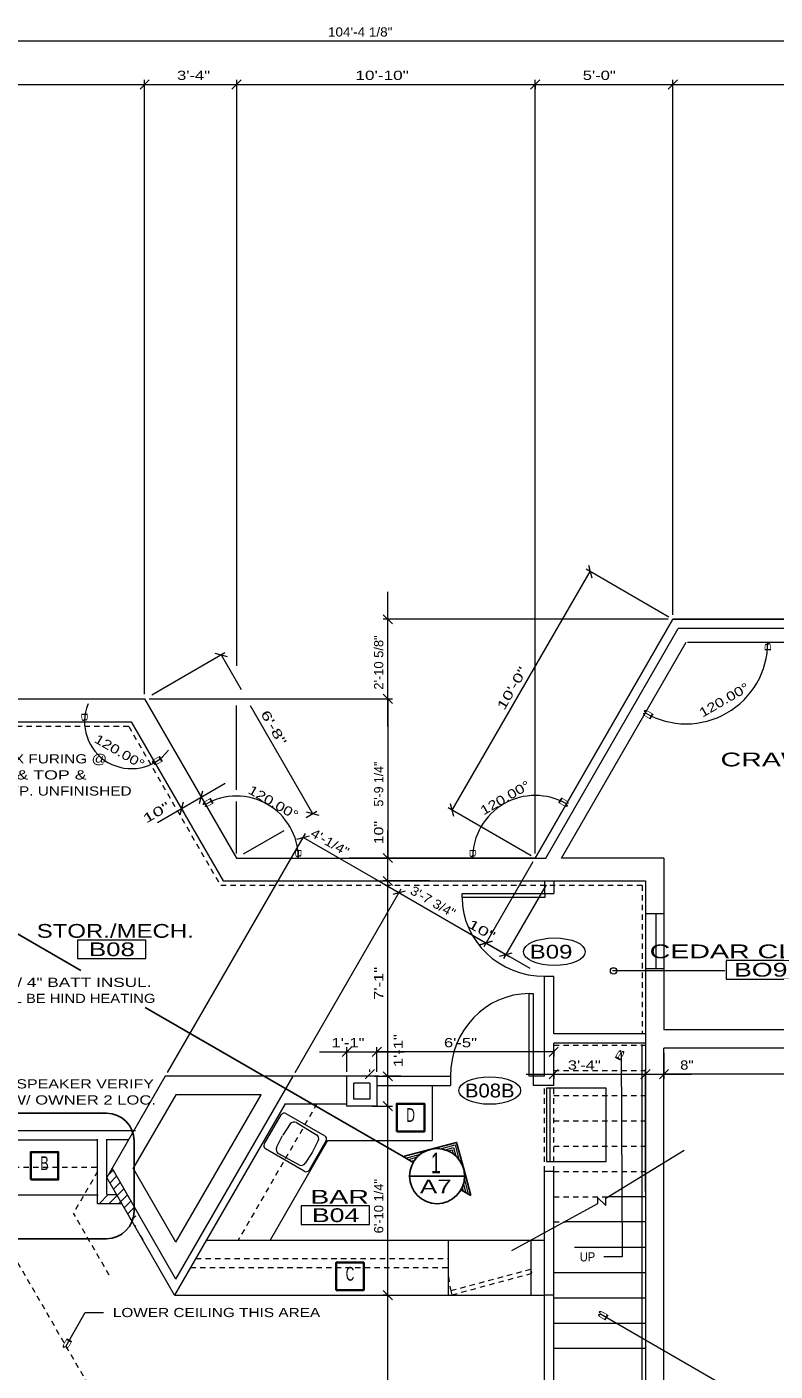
# Model space of a CAD drawing. Extents: x 7 to 126, y 6 to 93.
# Drawn here: x 56.6 to 83.75, y 44.6 to 93.37 of the extents above; entities that cross this region are included whole.
import ezdxf
from ezdxf.enums import TextEntityAlignment as Align

# ---------------------------------------------------------------- set-up
doc = ezdxf.new("R2010")
doc.units = 0
doc.header["$LTSCALE"] = 0.13
doc.linetypes.add('SHORT_DASHED', pattern=[2.7, 1.5, -1.2])
for name, color, linetype, lineweight in [('13', 7, 'Continuous', 13), ('14', 7, 'Continuous', 13), ('15', 7, 'Continuous', 13), ('17', 7, 'Continuous', 13), ('20', 7, 'Continuous', 13), ('22', 7, 'SHORT_DASHED', 13), ('24', 7, 'Continuous', 13), ('30', 7, 'Continuous', 13), ('35', 7, 'Continuous', 13), ('36', 7, 'Continuous', 13), ('40', 7, 'Continuous', 13), ('41', 7, 'Continuous', 13), ('42', 7, 'Continuous', 13), ('45', 7, 'Continuous', 13), ('50', 7, 'Continuous', 13), ('53', 7, 'Continuous', 13), ('56', 7, 'Continuous', 13), ('7', 7, 'Continuous', 13)]:
    doc.layers.add(name, color=color, linetype=linetype, lineweight=lineweight)

msp = doc.modelspace()

# ---------------------------------------------------------------- linework, layer by layer
at = {"layer": '13'}
msp.add_line((75.4239, 63.2187), (80.2315, 71.5456), dxfattribs=at)
msp.add_lwpolyline([(113.2426, 75.154), (98.9815, 75.154), (96.8981, 71.5456), (80.2315, 71.5456)], dxfattribs=at)
at = {"layer": '14'}
for p, q in [((61.6176, 55.2982), (59.4984, 51.6276)), ((68.1292, 55.2982), (61.6176, 55.2982)), ((69.3792, 55.2982), (68.1292, 55.2982)), ((69.2959, 55.2982), (69.2959, 54.2149)), ((68.4625, 54.4649), (68.4625, 55.0482)), ((69.0459, 55.0482), (68.4625, 55.0482)), ((69.0459, 55.0482), (69.0459, 54.4649)), ((65.9685, 54.2982), (68.2125, 54.2982)), ((69.0459, 54.4649), (68.4625, 54.4649)), ((60.7125, 49.5247), (60.8069, 49.3613))]:
    msp.add_line(p, q, dxfattribs=at)
for points in [[(115.8724, 34.3511), (77.539, 34.3511), (75.8724, 37.2379), (59.2057, 37.2379), (57.539, 34.3511), (40.8724, 34.3511), (16.7057, 76.209), (22.539, 86.3127), (34.2057, 86.3127), (44.2057, 68.9922), (60.8724, 68.9922)], [(113.4884, 75.4873), (98.789, 75.4873), (96.7057, 71.8789), (80.039, 71.8789), (75.039, 63.2187), (68.2977, 63.2187)], [(60.8724, 68.9922), (64.2057, 63.2187), (75.039, 63.2187)], [(69.2959, 54.2149), (68.2125, 54.2149), (68.2125, 55.2982)], [(65.9685, 54.2982), (61.9625, 47.3596), (59.4984, 51.6276)]]:
    msp.add_lwpolyline(points, dxfattribs=at)
at = {"layer": '15'}
for p, q in [((76.0013, 63.2187), (80.5226, 71.0498)), ((80.5729, 71.0456), (96.6563, 71.0456)), ((75.039, 63.2187), (75.4239, 63.2187)), ((79.7139, 63.2187), (76.0013, 63.2187)), ((79.7139, 63.2187), (79.7139, 56.9873)), ((63.7246, 62.3853), (79.0473, 62.3853)), ((79.0473, 62.3853), (79.0473, 38.0712)), ((79.0417, 61.2083), (79.6979, 61.2083)), ((79.4167, 61.2083), (79.4167, 59.2292)), ((79.0417, 59.2083), (79.6979, 59.2083)), ((93.7139, 56.9873), (79.7139, 56.9873)), ((94.3806, 56.3207), (79.7139, 56.3207)), ((79.7139, 37.4046), (79.7139, 56.3207)), ((62.0106, 47.943), (66.2572, 55.2982)), ((62.0106, 49.2763), (65.1025, 54.6315)), ((62.0106, 47.943), (59.6908, 51.961)), ((62.0106, 49.2763), (60.4606, 51.961))]:
    msp.add_line(p, q, dxfattribs=at)
for points in [[(23.2126, 85.4793), (33.7246, 85.4793), (43.7246, 68.1588), (60.3912, 68.1588), (63.7246, 62.3853)], [(65.1025, 54.6315), (62.0025, 54.6315), (60.4606, 51.961)]]:
    msp.add_lwpolyline(points, dxfattribs=at)
at = {"layer": '17'}
for points in [[(75.3958, 61.9271), (75.3958, 61.7812), (72.3958, 61.7812), (72.3958, 61.9271)], [(74.9679, 55.2982), (74.8221, 55.2982), (74.8221, 58.2982), (74.9679, 58.2982)]]:
    msp.add_lwpolyline(points, close=True, dxfattribs=at)
for centre, major_axis, start_param, end_param in [((75.3958, 61.7812), (-3, 0), 6.2831853, 7.8539816), ((74.8221, 55.2982), (0, 3), 0, 1.5707963)]:
    msp.add_ellipse(centre, major_axis=major_axis, ratio=0.951389, start_param=start_param, end_param=end_param, dxfattribs=at)
at = {"layer": '20', "linetype": 'SHORT_DASHED'}
for p, q in [((75.7139, 56.4313), (79.0473, 56.4313)), ((75.7139, 55.5146), (79.0473, 55.5146)), ((75.7139, 54.5979), (79.0473, 54.5979)), ((75.7139, 53.6813), (79.0473, 53.6813)), ((75.7139, 52.7646), (79.0473, 52.7646)), ((75.7139, 51.8479), (79.0473, 51.8479)), ((75.7139, 50.9313), (77.6979, 50.9313)), ((75.7139, 50.0146), (76.1562, 50.0146))]:
    msp.add_line(p, q, dxfattribs=at)
at = {"layer": '20'}
for p, q in [((79.0473, 50.9313), (77.6979, 50.9313)), ((79.0473, 50.0146), (76.1562, 50.0146)), ((76.464, 49.0979), (79.0473, 49.0979)), ((75.7139, 48.1813), (79.0473, 48.1813)), ((75.7139, 47.2646), (79.0473, 47.2646)), ((75.7139, 46.3479), (79.0473, 46.3479)), ((75.7139, 45.4313), (79.0473, 45.4313))]:
    msp.add_line(p, q, dxfattribs=at)
at = {"layer": '22'}
msp.add_line((55.0345, 50.6771), (61.6389, 39.2379), dxfattribs=at)
at = {"layer": '24', "linetype": 'SHORT_DASHED'}
for p, q in [((60.295, 67.9922), (43.4737, 67.9922)), ((60.295, 67.9922), (63.6283, 62.2187)), ((78.9223, 62.2187), (63.6283, 62.2187)), ((78.9223, 62.2187), (78.9223, 56.8542))]:
    msp.add_line(p, q, dxfattribs=at)
at = {"layer": '24'}
for p, q in [((78.9223, 38.2379), (78.9223, 56.4583)), ((75.7139, 42.5146), (75.7139, 47.375))]:
    msp.add_line(p, q, dxfattribs=at)
msp.add_lwpolyline([(75.7139, 42.5146), (75.3806, 42.5146), (75.3806, 47.375)], dxfattribs=at)
at = {"layer": '30'}
for p, q in [((65.2133, 52.8368), (65.83, 53.905)), ((66.0007, 53.9507), (67.408, 53.1382)), ((66.1557, 53.5703), (65.8872, 53.1684)), ((66.3793, 53.619), (67.1125, 53.1772)), ((65.663, 52.7169), (65.8768, 53.1504)), ((67.4538, 52.9675), (66.8371, 51.8993)), ((66.9577, 52.5504), (67.1741, 52.9571)), ((66.6663, 51.8535), (65.259, 52.666)), ((65.7326, 52.499), (66.4818, 52.0849)), ((66.9473, 52.5324), (66.7033, 52.1416))]:
    msp.add_line(p, q, dxfattribs=at)
for centre, radius, start, end in [((65.9383, 53.8425), 0.125, 60, 150), ((66.2933, 53.4762), 0.1667, 58.93024, 145.61656), ((67.0265, 53.0344), 0.1667, 332.33731, 58.93024), ((65.3215, 52.7743), 0.125, 150, 240), ((65.8133, 52.6449), 0.1667, 154.38344, 241.06976), ((67.3455, 53.03), 0.125, 330, 60), ((66.5625, 52.2308), 0.1667, 241.06976, 327.66269), ((66.7288, 51.9618), 0.125, 240, 330)]:
    msp.add_arc(centre, radius, start, end, dxfattribs=at)
at = {"layer": '35'}
for p, q in [((71.3013, 54.9649), (71.3013, 52.9649)), ((67.5081, 52.9649), (65.4266, 49.3596)), ((67.5081, 52.9649), (71.3013, 52.9649)), ((55.4271, 51), (59.1651, 51)), ((63.1172, 49.3596), (75.3806, 49.3596)), ((71.8806, 49.3596), (71.8806, 47.3768)), ((74.8806, 49.3596), (74.8806, 47.3768)), ((61.9625, 47.3596), (75.3806, 47.3596))]:
    msp.add_line(p, q, dxfattribs=at)
at = {"layer": '35', "linetype": 'SHORT_DASHED'}
for p, q in [((67.1232, 54.2982), (64.2719, 49.3596)), ((55.4271, 52), (59.1651, 52)), ((62.5399, 48.3596), (71.8806, 48.3596)), ((62.7323, 48.693), (71.8806, 48.693))]:
    msp.add_line(p, q, dxfattribs=at)
msp.add_lwpolyline([(74.9218, 48.1509), (74.8841, 48.2918), (71.9863, 47.5153), (72.024, 47.3744)], close=True, dxfattribs=at)
msp.add_ellipse((74.8841, 48.2918), major_axis=(-2.8978, -0.7765), ratio=0.951389, start_param=6.0980881, end_param=6.2831853, dxfattribs=at)
at = {"layer": '36'}
msp.add_line((75.5755, 54.8561), (75.5755, 52.2023), dxfattribs=at)
msp.add_line((75.5755, 54.8561), (75.5755, 52.2023), dxfattribs=at)
msp.add_lwpolyline([(75.4549, 52.2023), (77.6216, 52.2023), (77.6216, 54.8689), (75.4549, 54.8689)], close=True, dxfattribs=at)
msp.add_lwpolyline([(75.4549, 52.2023), (77.6216, 52.2023), (77.6216, 54.8689), (75.4549, 54.8689)], close=True, dxfattribs=at)
at = {"layer": '40', "lineweight": 25}
for p, q in [((44.0104, 67.5385), (58.5628, 59.1367)), ((70.2579, 52.3845), (60.8886, 57.7939)), ((50.3229, 53.9583), (59.4896, 53.9583)), ((60.4896, 52.9583), (60.4896, 50.4062)), ((70.2579, 52.3845), (71.2238, 52.6433)), ((70.2579, 52.3845), (70.6166, 52.1774)), ((72.4486, 51.9362), (72.7074, 50.9703)), ((70.4827, 51.6774), (72.4827, 51.6774)), ((72.3487, 51.1774), (72.7074, 50.9703)), ((59.4896, 49.4062), (50.3229, 49.4062))]:
    msp.add_line(p, q, dxfattribs=at)
at = {"layer": '40'}
for p, q in [((81.9167, 59.125), (77.8438, 59.125)), ((70.3498, 52.3315), (70.8762, 52.4726)), ((70.4416, 52.2785), (70.7538, 52.3621)), ((70.5335, 52.2254), (70.6716, 52.2624)), ((72.3948, 51.2676), (72.4318, 51.1294)), ((72.44, 51.3886), (72.5237, 51.0764)), ((72.4745, 51.5498), (72.6156, 51.0233))]:
    msp.add_line(p, q, dxfattribs=at)
at = {"layer": '40', "linetype": 'SHORT_DASHED'}
for p in [(59.1651, 51.8473), (59.5905, 48.0813)]:
    msp.add_line(p, (58.2906, 50.3328), dxfattribs=at)
at = {"layer": '40', "lineweight": 35}
for points in [[(70.0208, 53.3021), (71.0208, 53.3021), (71.0208, 54.3021), (70.0208, 54.3021)], [(56.7396, 51.5521), (57.7396, 51.5521), (57.7396, 52.5521), (56.7396, 52.5521)], [(67.8229, 47.5417), (68.8229, 47.5417), (68.8229, 48.5417), (67.8229, 48.5417)]]:
    msp.add_lwpolyline(points, close=True, dxfattribs=at)
at = {"layer": '40', "lineweight": 25}
msp.add_lwpolyline([(71.2238, 52.6433), (72.1898, 52.9022), (72.4486, 51.9362)], dxfattribs=at)
at = {"layer": '40'}
for points in [[(71.6103, 52.6692), (72.1367, 52.8103), (72.2778, 52.2838)], [(71.7715, 52.6348), (72.0837, 52.7184), (72.1674, 52.4062)], [(71.8925, 52.5896), (72.0307, 52.6266), (72.0677, 52.4884)]]:
    msp.add_lwpolyline(points, dxfattribs=at)
msp.add_circle((77.8854, 59.125), 0.1146, dxfattribs=at)
at = {"layer": '40', "lineweight": 25}
msp.add_circle((71.4827, 51.6774), 1, dxfattribs=at)
for centre, start, end in [((59.4896, 52.9583), 0, 90), ((59.4896, 50.4062), 270, 0)]:
    msp.add_arc(centre, 1, start, end, dxfattribs=at)
at = {"layer": '41'}
msp.add_lwpolyline([(74.1968, 48.9808), (77.3168, 50.6859), (77.3168, 50.8957), (77.6034, 50.6091), (77.6034, 50.8792), (80.4428, 52.6148)], dxfattribs=at)
at = {"layer": '42'}
for centre in [(75.7394, 59.8195), (73.394, 54.7829)]:
    msp.add_ellipse(centre, major_axis=(1.1204, 0), ratio=0.446291, dxfattribs=at)
at = {"layer": '45'}
for points in [[(58.4373, 59.5704), (60.9224, 59.5704), (60.9224, 60.2411), (58.4373, 60.2411)], [(81.9754, 58.8277), (84.4605, 58.8277), (84.4605, 59.4984), (81.9754, 59.4984)], [(66.5521, 49.9231), (69.0373, 49.9231), (69.0373, 50.5938), (66.5521, 50.5938)]]:
    msp.add_lwpolyline(points, close=True, dxfattribs=at)
at = {"layer": '50'}
for p, q in [((121.0473, 92.8542), (16.7057, 92.8542)), ((44.2057, 91.2812), (60.8724, 91.2812)), ((59.8724, 91.2812), (65.2057, 91.2812)), ((61.039, 91.4479), (60.7057, 91.1146)), ((61.039, 91.4479), (60.7057, 91.1146)), ((60.8724, 69.1588), (60.8724, 91.4479)), ((64.039, 91.1146), (64.3724, 91.4479)), ((64.039, 91.1146), (64.3724, 91.4479)), ((64.2057, 91.4479), (64.2057, 70.1875)), ((64.2057, 91.2812), (75.039, 91.2812)), ((74.8724, 91.1146), (75.2057, 91.4479)), ((75.2057, 91.4479), (74.8724, 91.1146)), ((75.039, 63.3853), (75.039, 91.4479)), ((75.039, 91.2812), (80.039, 91.2812)), ((75.039, 91.2812), (75.039, 91.1146)), ((80.2057, 91.4479), (79.8724, 91.1146)), ((79.8724, 91.1146), (80.2057, 91.4479)), ((80.039, 72.0456), (80.039, 91.4479)), ((80.039, 91.2812), (96.7057, 91.2812)), ((79.8947, 71.9622), (76.889, 73.6976)), ((76.9723, 73.8419), (77.0944, 73.3866)), ((72.0333, 64.954), (77.0333, 73.6142)), ((69.6979, 67.9922), (69.6979, 72.8789)), ((69.8646, 71.7122), (69.5312, 72.0456)), ((79.8724, 71.8789), (69.5312, 71.8789)), ((61.1305, 69.1412), (63.7885, 70.6758)), ((63.4165, 70.6535), (63.8719, 70.5315)), ((63.6442, 70.5925), (64.3735, 69.3293)), ((61.039, 68.9922), (69.8646, 68.9922)), ((69.5312, 69.1588), (69.8646, 68.8255)), ((69.5312, 69.1588), (69.8646, 68.8255)), ((69.6979, 68.9922), (69.6979, 63.2187)), ((64.2057, 65.6875), (64.2057, 68.75)), ((66.9775, 64.819), (64.7107, 68.7453)), ((61.3421, 64.5119), (63.7958, 65.9286)), ((62.6224, 65.9611), (63.0131, 65.2843)), ((62.8688, 65.2009), (62.9908, 65.6563)), ((62.1412, 65.1277), (62.2914, 64.8676)), ((62.2691, 65.2396), (62.1471, 64.7843)), ((64.2057, 63.3853), (64.2057, 65.2708)), ((67.1219, 64.9023), (66.7307, 64.6765)), ((67.2052, 64.758), (66.7499, 64.88)), ((74.8947, 63.302), (71.889, 65.0373)), ((72.0944, 64.7263), (71.9723, 65.1817)), ((61.7009, 55.4425), (66.7059, 64.1114)), ((64.4639, 63.3677), (65.9331, 64.216)), ((66.3949, 63.906), (66.8502, 64.028)), ((70.1022, 61.958), (66.6226, 63.967)), ((69.6979, 61.3853), (69.6979, 64.2187)), ((69.8646, 63.052), (69.5312, 63.3853)), ((69.8646, 63.052), (69.5312, 63.3853)), ((69.789, 63.2187), (69.8646, 63.2187)), ((74.9557, 63.0743), (73.1756, 59.9912)), ((69.2362, 62.458), (74.125, 59.6355)), ((69.5312, 62.552), (69.8646, 62.2187)), ((69.5312, 62.552), (69.8646, 62.2187)), ((69.5312, 62.552), (69.8646, 62.2187)), ((66.3405, 55.4425), (70.1856, 62.1024)), ((71.2192, 62.3853), (69.5312, 62.3853)), ((69.6979, 55.2982), (69.6979, 62.3853)), ((69.789, 62.3853), (69.8646, 62.3853)), ((70.3299, 62.019), (69.8746, 61.897)), ((70.3299, 62.019), (69.8746, 61.897)), ((75.4368, 62.241), (73.8973, 59.5745)), ((72.3929, 60.6355), (74.8467, 59.2188)), ((73.4866, 60.1965), (73.0313, 60.0745)), ((73.0313, 60.0745), (73.4866, 60.1965)), ((73.753, 59.6578), (74.2083, 59.7798)), ((73.753, 59.6578), (74.2083, 59.7798)), ((67.2125, 56.1875), (70.2959, 56.1875)), ((68.3792, 56.3542), (68.0459, 56.0208)), ((68.2125, 55.4649), (68.2125, 56.3542)), ((69.1292, 56.0208), (69.4625, 56.3542)), ((69.1292, 56.0208), (69.4625, 56.3542)), ((69.2959, 55.4649), (69.2959, 56.3542)), ((75.7139, 56.1875), (69.2959, 56.1875)), ((69.6979, 53.2149), (69.6979, 56.2982)), ((75.8806, 56.3542), (75.5473, 56.0208)), ((75.7139, 56.2646), (75.7139, 56.0208)), ((79.7139, 56.154), (79.7139, 55.2083)), ((68.8792, 55.2083), (69.2125, 55.5417)), ((69.0459, 55.4649), (69.0459, 55.5417)), ((69.2125, 55.2982), (69.8646, 55.2982)), ((69.8646, 55.1315), (69.5312, 55.4649)), ((69.8646, 55.1315), (69.5312, 55.4649)), ((69.8646, 55.1315), (69.5312, 55.4649)), ((70.174, 55.2982), (69.5312, 55.2982)), ((69.6979, 53.0482), (69.6979, 55.2982)), ((74.7139, 55.375), (80.0473, 55.375)), ((75.8806, 55.5417), (75.5473, 55.2083)), ((75.8806, 55.5417), (75.5473, 55.2083)), ((75.7139, 55.3479), (75.7139, 55.2083)), ((78.0473, 55.375), (80.7139, 55.375)), ((79.2139, 55.5417), (78.8806, 55.2083)), ((78.8806, 55.2083), (79.2139, 55.5417)), ((79.0473, 51.1166), (79.0473, 55.5417)), ((79.5473, 55.2083), (79.8806, 55.5417)), ((79.5473, 55.2083), (79.8806, 55.5417)), ((93.7139, 55.375), (79.7139, 55.375)), ((69.1292, 54.2149), (69.8646, 54.2149)), ((69.5312, 54.3815), (69.8646, 54.0482)), ((69.5312, 54.3815), (69.8646, 54.0482)), ((69.6979, 47.3596), (69.6979, 54.2149)), ((62.1292, 47.3596), (69.8646, 47.3596)), ((69.5312, 47.5263), (69.8646, 47.193)), ((69.8646, 47.193), (69.5312, 47.5263)), ((69.5312, 47.5263), (69.8646, 47.193)), ((69.6979, 47.3596), (69.5312, 47.3596)), ((69.6979, 38.0712), (69.6979, 47.3596))]:
    msp.add_line(p, q, dxfattribs=at)
for points in [[(78.1667, 56.1667), (78.1936, 48.7494), (77.5269, 48.7494)], [(58.0104, 45.5), (58.7202, 46.7294), (59.3869, 46.7294)], [(77.4062, 46.6771), (82.7784, 43.5755), (83.4451, 43.5755)]]:
    msp.add_lwpolyline(points, dxfattribs=at)
for centre, radius, start, end in [((80.5202, 71.0456), 2.9601, 239.99997, 0), ((60.3912, 68.1588), 1.6973, 157.49552, 322.50458), ((64.2057, 63.2187), 2.2466, 0, 119.99992), ((75.039, 63.2187), 2.2684, 59.99997, 180)]:
    msp.add_arc(centre, radius, start, end, dxfattribs=at)
at = {"layer": '53'}
for p, q in [((75.3806, 62.375), (75.3806, 61.9271)), ((75.7139, 62.375), (75.7139, 61.9271)), ((75.3806, 61.9271), (75.7139, 61.9271)), ((75.3806, 58.9271), (75.7188, 58.9271)), ((75.3806, 55.2982), (75.3806, 58.9271)), ((75.7139, 56.8369), (75.7139, 58.9271)), ((79.0473, 56.8369), (75.7139, 56.8369)), ((79.0473, 56.5036), (75.7139, 56.5036)), ((75.7139, 54.9649), (75.7139, 56.5036)), ((69.3792, 55.2982), (71.9688, 55.2982)), ((71.9679, 55.2982), (71.9679, 54.9649)), ((74.9679, 55.2982), (74.9679, 54.9649)), ((75.3806, 55.2982), (74.9679, 55.2982)), ((69.2959, 54.9649), (71.9679, 54.9649)), ((75.7139, 54.9649), (74.9679, 54.9649)), ((54.9271, 53.3333), (60.5417, 53.3333)), ((60.2907, 53), (59.4896, 53)), ((59.4984, 51.0104), (59.4984, 53.0176)), ((75.3806, 47.375), (75.3806, 51.8479)), ((75.7139, 51.8479), (75.3806, 51.8479)), ((75.7139, 47.375), (75.7139, 51.8479)), ((59.4984, 51.0104), (59.8547, 51.0104)), ((75.3806, 47.375), (75.7043, 47.375))]:
    msp.add_line(p, q, dxfattribs=at)
at = {"layer": '53', "linetype": 'SHORT_DASHED'}
for p, q in [((75.3806, 51.8479), (75.3806, 54.9649)), ((75.7139, 51.8479), (75.7139, 54.9649))]:
    msp.add_line(p, q, dxfattribs=at)
at = {"layer": '53'}
for points in [[(55.4271, 50.6771), (55.4271, 53), (59.1651, 53)], [(60.0417, 50.6771), (59.1651, 50.6771), (59.1651, 53.0176)]]:
    msp.add_lwpolyline(points, dxfattribs=at)
at = {"layer": '56'}
for p, q in [((59.5474, 51.7126), (59.7293, 51.8944)), ((59.5726, 50.6771), (60.1175, 51.222)), ((59.6147, 51.4262), (59.8587, 51.6703)), ((59.7441, 51.2021), (59.9881, 51.4461)), ((59.1651, 50.9766), (59.1888, 51.0004)), ((59.2191, 50.6771), (59.5478, 51.0058)), ((59.9262, 50.6771), (60.2469, 50.9978)), ((60.1294, 50.5268), (60.3763, 50.7737)), ((60.2597, 50.3035), (60.5057, 50.5495)), ((60.39, 50.0803), (60.5505, 50.2407)), ((60.5203, 49.857), (60.5505, 49.8872))]:
    msp.add_line(p, q, dxfattribs=at)
at = {"layer": '7'}
msp.add_lwpolyline([(115.8724, 34.3511), (77.539, 34.3511), (75.8724, 37.2379), (59.2057, 37.2379), (57.539, 34.3511), (40.8724, 34.3511), (16.7057, 76.209), (22.539, 86.3127), (34.2057, 86.3127), (44.2057, 68.9922), (60.8724, 68.9922), (64.2057, 63.2187), (65.039, 63.2187), (75.039, 63.2187), (80.039, 71.8789), (96.7057, 71.8789), (98.789, 75.4873), (113.4884, 75.4873), (121.0473, 51.0685)], dxfattribs=at)

# ---------------------------------------------------------------- texts
at = {"layer": '40'}
for s, width, p in [('D', 0.65, (70.3665, 53.6441)), ('B', 0.7, (57.0852, 51.8941)), ('C', 0.65, (68.1686, 47.8837))]:
    msp.add_text(s, height=0.5, dxfattribs=dict(at, width=width)).set_placement(p)
for s, height, width, p in [('1', 0.75, 0.65, (71.4389, 51.7785)), ('A7 ', 0.5, 1.4, (71.5649, 51.0524))]:
    msp.add_text(s, height=height, dxfattribs=dict(at, width=width)).set_placement(p, align=Align.CENTER)
at = {"layer": '42'}
for s, width, p in [('B09 ', 1.3, (75.7394, 59.5695)), ('B08B', 1.1, (73.394, 54.5329))]:
    msp.add_text(s, height=0.5, dxfattribs=dict(at, width=width)).set_placement(p, align=Align.CENTER)
at = {"layer": '45'}
for s, width, p in [('     CRAWL SPACE    ', 1.55, (85.3956, 66.5432)), ('     STOR./MECH.    ', 1.3, (59.6873, 60.3244)), (' B08 ', 1.4, (59.6873, 59.6578)), ('    CEDAR CLOSET    ', 1.55, (83.2254, 59.5817)), (' BO9 ', 1.45, (83.2253, 58.915)), ('         BAR        ', 1.55, (67.8021, 50.6771)), (' B04 ', 1.45, (67.8021, 50.0104))]:
    msp.add_text(s, height=0.5, dxfattribs=dict(at, width=width)).set_placement(p, align=Align.CENTER)
at = {"layer": '50'}
for s, width, p in [('104\'-4 1/8"', 1.1, (67.5248, 93.0208)), ('3\'-4"', 1.35, (62.0494, 91.4479)), ('10\'-10"', 1.4, (68.52, 91.4479)), ('5\'-0"', 1.35, (76.7674, 91.4479)), ('TREATED 2X FURING @ ', 1.25, (53.0658, 66.6506)), ('2\' -0" O.C. & TOP & ', 1.45, (53.0658, 66.0673)), ('BOTTOM TYP. UNFINISHED', 1.25, (53.0658, 65.484)), ('1/2\' G.B. B.S. 2X4 W/ 4" BATT INSUL. ', 1.4, (50.4479, 58.5417)), ('FOR SOUND CONTROL BE HIND HEATING ', 1.2, (50.4479, 57.9583)), ('1\'-1"', 1.35, (67.654, 56.3542)), ('6\'-5"', 1.35, (71.7332, 56.3542)), ('3\'-4"', 1.35, (76.2246, 55.5417)), ('8"', 1.2, (80.3021, 55.5417)), ('BUILT-IN STERO SPEAKER VERIFY ', 1.3, (51.4883, 54.8586)), ('SIZE AND LOC. W/ OWNER 2 LOC. ', 1.35, (51.4883, 54.2753)), ('UP', 0.9, (76.6617, 48.5827)), ('LOWER CEILING THIS AREA', 1.25, (59.7202, 46.5627))]:
    msp.add_text(s, height=0.3333, dxfattribs=dict(at, width=width)).set_placement(p)
for s, rotation, width, p in [('2\'-10 5/8"', 90, 1.05, (69.5312, 69.3255)), ('10\'-0"', 60, 1.5, (73.9205, 68.556)), ('120.00°', 30, 1.3, (81.1115, 68.3077)), ('6\'-8"', 300, 1.55, (65.0694, 68.4573)), ('120.00°', 330, 1.3, (59.0145, 67.4377)), ('120.00°', 30, 1.3, (73.1693, 64.7609)), ('120.00°', 330, 1.3, (64.5952, 65.5887)), ('10"', 30, 1.6, (60.9313, 64.4672)), ('10"', 90, 1.3, (69.5312, 63.7141)), ('4\'-1/4"', 330, 1.2, (66.8621, 64.0212)), ('3\'-7 3/4"', 330, 1.1, (70.4742, 61.9357)), ('10"', 330, 1.6, (72.5644, 60.7289)), ('7\'-1"', 90, 1.35, (69.5312, 58.0701)), ('1\'-1"', 90, 1.35, (70.2396, 55.6315)), ('6\'-10 1/4"', 90, 1.05, (69.5312, 49.6009))]:
    msp.add_text(s, height=0.3333, rotation=rotation, dxfattribs=dict(at, width=width)).set_placement(p)
for rotation, width, p in [(90, 1.7, (83.5914, 71.0456)), (270, 1.7, (58.5828, 68.1588)), (150, 2.35, (78.9845, 68.6424)), (210, 2.35, (61.0732, 66.721)), (210, 2.35, (62.9157, 65.1964)), (330, 2.35, (76.2288, 65.0227)), (270, 1.7, (66.3412, 63.2187)), (270, 1.7, (72.6596, 63.2187)), (60, 2.35, (78.327, 56.2222)), (150, 2.35, (77.3507, 46.8375)), (240, 2.35, (57.85, 45.4444))]:
    msp.add_text('B', height=0.2222, rotation=rotation, dxfattribs=dict(at, width=width)).set_placement(p, align=Align.RIGHT)
msp.add_text('5\'-9 1/4"', height=0.3333, rotation=90, dxfattribs=at).set_placement((69.5312, 65.0844))

doc.saveas('drawing.dxf')
